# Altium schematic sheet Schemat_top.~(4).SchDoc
size A4; Author: Michał Wojna; CompanyName: AGH; Revision: 1
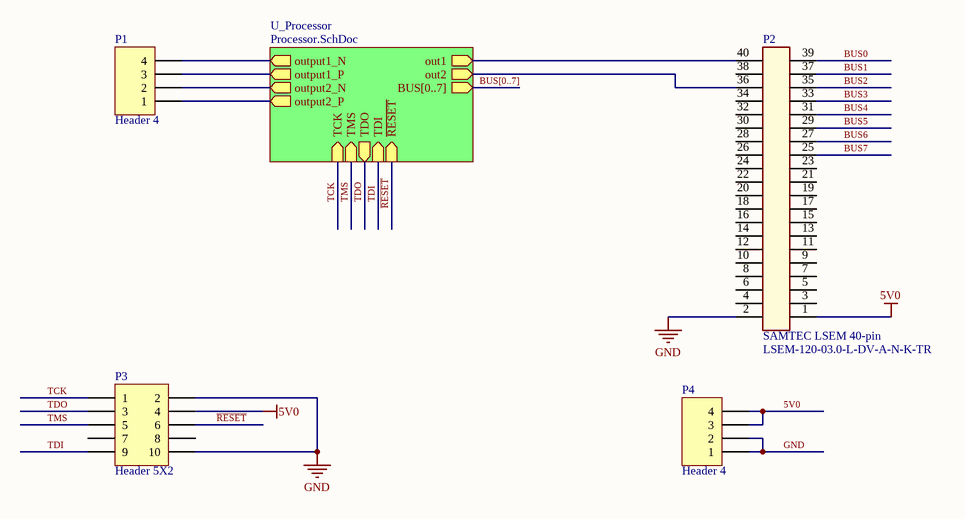
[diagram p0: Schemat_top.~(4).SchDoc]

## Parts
P1  Header 4  [HDR1X4]
P2  SAMTEC LSEM 40-pin  [LSEM-120-03.0-L-DV-A-N-K-TR]
P3  Header 5X2  [HDR2X5]
P4  Header 4  [HDR1X4]

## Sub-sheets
U_Processor = Processor.SchDoc: out1 (out), out2 (out), TCK (in), TMS (in), TDO (out), TDI (in), ~{RESET} (in), BUS[0..7] (out), output1_N (out), output1_P (out), output2_N (out), output2_P (out)

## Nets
5V0: P2.1(PIN) P3.4 P4.3 P4.4
GND: P2.2 P3.2 P3.10 P4.1 P4.2
BUS0: P2.39(PIN)
BUS1: P2.37(PIN)
BUS2: P2.35(PIN)
BUS3: P2.33(PIN)
BUS4: P2.31(PIN)
BUS5: P2.29(PIN)
BUS6: P2.27(PIN)
BUS7: P2.25(PIN)
~{RESET}: P3.6 ; sheet U_Processor/~{RESET}
TCK: P3.1 ; sheet U_Processor/TCK
TDI: P3.9 ; sheet U_Processor/TDI
TDO: P3.3 ; sheet U_Processor/TDO
TMS: P3.5 ; sheet U_Processor/TMS
NetP1_1: P1.1 ; sheet U_Processor/output2_P
NetP1_2: P1.2 ; sheet U_Processor/output2_N
NetP1_3: P1.3 ; sheet U_Processor/output1_P
NetP1_4: P1.4 ; sheet U_Processor/output1_N
NetP2_36: P2.36 ; sheet U_Processor/out2
NetP2_40: P2.40 ; sheet U_Processor/out1

Not connected (* = marked no-connect by the designer): P2 3(PIN) 4(3) 5(PIN) 6(4) 7(PIN) 8(5) 9(PIN) 10(6) 11(PIN) 12(7) 13(PIN) 14(8) 15(PIN) 16(9) 17(PIN) 18(10) 19(PIN) 20(11) 21(PIN) 22(12) 23(PIN) 24(13) 26(14) 28(15) 30(16) 32(17) 34(18) 38(20); P3 7 8

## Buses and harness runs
bus BUS[0..7] = sheet U_Processor/BUS[0..7]

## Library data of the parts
P1 P4 = Header 4: Header, 4-Pin
P2 = SAMTEC LSEM 40-pin: Component desciption
P3 = Header 5X2: Header, 5-Pin, Dual row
